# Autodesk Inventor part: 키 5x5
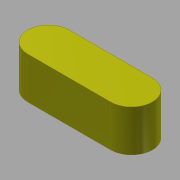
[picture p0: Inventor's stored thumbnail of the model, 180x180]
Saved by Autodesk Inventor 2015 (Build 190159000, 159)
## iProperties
Created: 2011-04
Part Number: 키 5x5
Document SubType Name: Modeling
Designer: pww
Density: 7.86 g/cm^3
Material: 강철, 연강
Appearance: 노란색
Author: pww
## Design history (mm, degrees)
sketch "스케치1"
  geometry: L1 (-5, -2.5)-(5, -2.5); L2 (5, 2.5)-(-5, 2.5); A1 r 2.5 centre (-5, 0) between (-5, 2.5) and (-5, -2.5); A2 r 2.5 centre (5, 0) between (5, -2.5) and (5, 2.5); 1 further point
  constraints: 4 end point, 4 point on circle, 2 centre point
extrude "돌출1" new body sketch "스케치1" distance "d0" = 5; taper "d1" = 0 deg
node "솔리드1"
